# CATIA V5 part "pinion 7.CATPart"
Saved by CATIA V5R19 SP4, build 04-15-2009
Part number: pinion 7
Bounding box of the stored display mesh (mm): x 0 to 22.15, y -51.133 to 51.133, z -51.133 to 51.133
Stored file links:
  G:\EU_thinkMotion\CFAO_2010\MMS_groupe1\MMS_groupe1\A reprendre\OK\rdeneffle\pinion 7.CATPart
  G:\EU_thinkMotion\CFAO_2010\MMS_groupe1\MMS_groupe1\A reprendre\OK\rdeneffle\pinion 2.CATPart
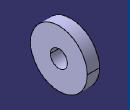
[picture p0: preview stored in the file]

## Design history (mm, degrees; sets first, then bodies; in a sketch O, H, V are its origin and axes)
Parameters
  `rayon interieur` = 15.505 mm
  `rayon extérieur` = 35.556 mm
  `rayon interieur.1` = 15.505 mm
  `rayon extérieur.1` = 51.133 mm
Body1 (main body)
Body2
  Sketch1 on yz-plane, origin (0, 0, 0), H (0, 1, 0), V (0, 0, 1)
    circle A1 centre (0, 0) radius 15.505
    circle A2 centre (0, 0) radius 51.133
    radius A2 = 51.133 {= `rayon extérieur.1`}
    radius A1 = 15.505 {= `rayon interieur.1`}
  Pad1: profile Sketch1, direction (1, 0, 0), length 22.15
